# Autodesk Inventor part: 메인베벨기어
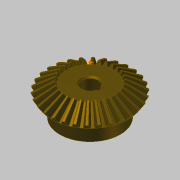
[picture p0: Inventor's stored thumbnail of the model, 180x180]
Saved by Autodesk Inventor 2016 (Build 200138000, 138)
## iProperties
Created: 2018-09
Part Number: 메인베벨기어
Material: 강철, 탄소
Document SubType Name: Modeling
Categories: <?xml version="1.0" encoding="UTF-16"?> <MemberInstance><Categories><FamilyTemplate><FamilyTemplateParameter ValueType="xs:double" Id="1" ObjectReferenceKey="da
Mass: 290.333 g
Surface Area: 107.709 cm^2
Volume: 36.8911 cm^3
Density: 7.87 g/cm^3
Appearance: 얼룩무늬
CustomPartVersion: 1
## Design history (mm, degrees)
node "맨 위 점"
node "메쉬 평면2"
sketch "톱니 본체 스케치"
  geometry: L1 (0, 0)-(28.669, -21.997); L2 (28.669, -21.997)-(31.109, -18.336); L3 (31.109, -18.336)-(0, 0); L4 (30, -20)-(0, 0); L5 (17.219, -13.212)-(18.685, -11.013); L6 (28.669, -21.997)-(17.219, -13.212); L7 (31.109, -18.336)-(18.685, -11.013); L8 (0, -39.387)-(0, 6.564) reference; L9 (0, -20)-(31.109, -20)
  constraints: 16 end point, 4 point on line, 3 perpendicular, 2 collinear, 1 horizontal alignment, 1 vertical alignment
  dimensions: "d0" = 60 diameter of L4.start L8 (= da_de); "d1" = 57.33744 diameter of L1.end L8 (= da_dfe); "d2" = 62.2188 diameter of L2.end L8 (= da_dae); "d3" = 14.4 distance between parallel lines of L2 L5 (= da_b); "d4" = 18.3359 vertical distance of L2.end L1.start (= da_ve)
revolve "톱니 본체" sketch "톱니 본체 스케치" stored, may be unused: angle "d5" = 90 deg
node "시작점"
node "톱니 평면"
sketch "시작 스케치"
  geometry: L1 (0, -23.505)-(0, 10.645) reference; L2 (-0.709, -2.928)-(0.709, -2.928); A1 r 19.188 centre (-19.457, -7.014) between (-0.709, -2.928) and (-3.232, 3.229); A2 r 19.188 centre (19.457, -7.014) between (3.232, 3.229) and (0.709, -2.928); A3 r 57.403 centre (0, -54.083) between (3.232, 3.229) and (-3.232, 3.229); 1 further point
  constraints: 6 point on circle, 3 centre point, 3 symmetric about line, 2 end point, 1 coincident, 1 perpendicular, 1 other
  dimensions: "d7" = 19.18795 radius of A1 (= fd_rr); "d8" = 19.45712 horizontal distance of point (0, -54.083) A1.centre (= fd_x); "d9" = 47.06905 vertical distance of point (0, -54.083) A1.centre (= fd_y); "d57" = 57.40327 radius of A3 (= 0.5 x fd_dva + 0.3 x da_he); "d58" = 51.15527 distance from line of A3.centre L2 (= 0.5 x fd_dva - 1.12 x da_he)
node "끝점"
  node "끝 평면"
sketch "3D 스케치 오른쪽"
  node "Helical Curve Right" dims "d65" = 229.90621 (computed from da_dm, da_delta, da_beta), "d66" = 31.5, "d67" = 60 (= da_de), "d68" = -9.82794 (= -da_delta), "d69" = 8.10972 (computed from fd_loft, da_delta)
node "끝 평면 오른쪽"
sketch "끝 스케치 오른쪽"
  geometry: L1 (0, -41.54)-(0, 13.178) reference; L2 (-0.422, -1.69)-(0.422, -1.69); A1 r 11.427 centre (-11.587, -4.123) between (-0.422, -1.69) and (-1.925, 1.977); A2 r 11.427 centre (11.587, -4.123) between (1.925, 1.977) and (0.422, -1.69); A3 r 34.184 centre (0, -32.153) between (1.925, 1.977) and (-1.925, 1.977); 1 further point
  constraints: 6 point on circle, 3 centre point, 3 symmetric about line, 2 end point, 1 coincident, 1 perpendicular, 1 other
  dimensions: "d70" = 11.58699 horizontal distance of A3.centre A1.centre (computed from fd_x, fd_ratio); "d71" = 28.03028 vertical distance of point (0, -32.153) A1.centre (computed from fd_y, fd_ratio); "d72" = 11.4267 radius of A1 (computed from fd_rr, fd_ratio); "d73" = 30.46369 distance from line of point (0, -32.153) L2 (computed from d58, fd_ratio); "d74" = 34.18446 radius of A3 (computed from d57, fd_ratio)
feature "로프트 오른쪽" sketch "끝 스케치 오른쪽" dims "d75" = 0, "d77" = 0, "d79" = 0, "d80" = 90 deg, "d85" = 20, "d92" = 90 deg, "d93" = 90 deg, "da_teethtype" = 0 [user parameter]
sketch "3D 스케치 왼쪽"
  node "Helical Curve Left" dims "d26" = 229.90621 (computed from da_dm, da_delta, da_beta), "d27" = 8.10972 (computed from fd_loft, da_delta), "d28" = 60 (= da_de), "d29" = -9.82794 (= -da_delta)
node "끝 평면 왼쪽"
sketch "끝 스케치 왼쪽" dims "d56" = 10.3728 (derived)
  geometry: L1 (0, -43.753)-(0, 15.405) reference; L2 (-0.422, -1.678)-(0.422, -1.678); A1 r 11.427 centre (-11.587, -4.111) between (-0.422, -1.678) and (-1.925, 1.988); A2 r 11.427 centre (11.587, -4.111) between (1.925, 1.988) and (0.422, -1.678); A3 r 34.184 centre (0, -32.142) between (1.925, 1.988) and (-1.925, 1.988); 2 further points; 1 other entity
  constraints: 6 point on circle, 3 centre point, 3 symmetric about line, 2 end point, 1 coincident, 2 other
  dimensions: "d30" = 11.4267 radius of A1 (computed from fd_rr, fd_ratio); "d31" = 11.58699 horizontal distance of point (0, -32.142) A1.centre (computed from fd_x, fd_ratio); "d32" = 28.03028 vertical distance of A1.centre point (0, -32.142) (computed from fd_y, fd_ratio); "d61" = 34.18446 radius of A3 (computed from d57, fd_ratio); "d62" = 30.46369 distance from line of point (0, -32.142) L2 (computed from d58, fd_ratio)
feature "로프트 왼쪽" sketch "끝 스케치 왼쪽" dims "d35" = 0, "d37" = 0, "d39" = 0, "d40" = 90 deg, "d84" = 10, "d90" = 90 deg, "d91" = 90 deg, "da_teethtype" = 0 [user parameter]
sketch "본체 스케치"
  geometry: L1 (0, -35.038)-(0, -19.531) reference; L2 (28.669, -21.997)-(17.219, -13.212) reference; L3 (17.219, -13.212)-(0, -13.212); L4 (28.669, -21.997)-(0, -21.997)
  constraints: 4 end point, 2 perpendicular, 2 point on line
revolve "본체 고정" sketch "본체 스케치" stored, may be unused: angle "d46" = 90 deg
feature "피치 지름" dims angle "d47" = 90 deg
sketch "스케치8"
  geometry: C1 r 22.5 at (0, 0); 1 further point
  constraints: 1 centre point, 1 coincident
  dimensions: "d94" = 45 diameter of C1
extrude "돌출1" join sketch "스케치8" distance "d95" = 13; taper "d96" = 0 deg
sketch "스케치9"
  geometry: 1 further point
hole "구멍1" sketch "스케치9" at (0, 0) diameter "d97" = 12; stored, may be unused: countersink angle "d101" = 90 deg, drill point angle "d103" = 118 deg; dims "d98" = 6, "d99" = 4, "d100" = 2, "d102" = 8
sketch "스케치10"
  geometry: L1 (5.657, 2)-(7.8, 2); L2 (7.8, 2)-(7.8, -2); L3 (7.8, -2)-(5.657, -2); A1 r 6 centre (0, 0) between (5.657, 2) and (5.657, -2) reference; 1 further point
  constraints: 6 end point, 2 parallel, 2 point on circle, 1 horizontal, 1 perpendicular
  dimensions: "d104" = 4 distance of L1.end L2.end; "d112" = 13.8 dimension on A1 L2
extrude "돌출2" cut sketch "스케치10" stored distance "d106" = 10; taper "d107" = 0 deg
chamfer "모따기1" distance "d108" = 1; stored, may be unused: second distance "d109" = 2, angle "d110" = 45 deg
fillet "모깎기1" dims "d111" = 2
body "Solid1"
feature "로프트" dims "d17" = 0, "d18" = 90 deg, "d19" = 0, "d20" = 90 deg, "d89" = 0, "da_teethtype" = 0 [user parameter]
pattern_circular "원형 패턴" dims angle "d22" = 360 deg, "d88" = 0, "da_teethtype" = 0 [user parameter]
pattern_circular "원형 패턴 오른쪽" dims angle "d82" = 360 deg, "da_teethtype" = 0 [user parameter]
pattern_circular "원형 패턴 왼쪽" dims angle "d42" = 360 deg, "da_teethtype" = 0 [user parameter]
sketch "끝 스케치"
  geometry: L1 (0, -15.359)-(0, 6.983) reference; L2 (-0.422, -1.69)-(0.422, -1.69); A1 r 11.427 centre (-11.587, -4.123) between (-0.422, -1.69) and (-1.925, 1.977); A2 r 11.427 centre (11.587, -4.123) between (1.925, 1.977) and (0.422, -1.69); A3 r 34.184 centre (0, -32.153) between (1.925, 1.977) and (-1.925, 1.977); 1 further point
  constraints: 6 point on circle, 3 centre point, 3 symmetric about line, 2 end point, 1 coincident, 1 other
  dimensions: "d12" = 11.4267 radius of A1 (computed from fd_rr, fd_ratio); "d15" = 11.58699 horizontal distance of A1.centre point (0, -32.153) (computed from fd_x, fd_ratio); "d16" = 28.03028 vertical distance of A1.centre point (0, -32.153) (computed from fd_y, fd_ratio); "d59" = 34.18446 radius of A3 (computed from d57, fd_ratio); "d60" = 30.46369 distance from line of A3.centre L2 (computed from d58, fd_ratio)
sketch "Sketch6"
  geometry: L1 (30, -20)-(0, 0) reference; L2 (0, -37.8)-(0, 6.3) reference
body "Srf1"
other parameters: "da_b" = 14.4 [user parameter; used in 2 equation terms], "da_de" = 60 [user parameter; used in 4 equation terms], "da_dae" = 62.2188 [user parameter; used in 2 equation terms], "da_dfe" = 57.33744 [user parameter; used in 1 equation term], "da_le" = 36.05551 [user parameter; used in 1 equation term], "da_omega" = 90 deg [user parameter; used in 1 equation term], "da_beta" = 0 [user parameter; used in 2 equation terms], "da_delta" = 9.82794 [user parameter; used in 8 equation terms], "da_alpha" = 20 deg [user parameter; used in 2 equation terms], "da_he" = 4.4 [user parameter; used in 4 equation terms], "da_ve" = 18.3359 [user parameter; used in 1 equation term], "fd_dv" = 108.16654 (computed from da_de, da_delta) [user parameter; used in 1 equation term], "fd_dva" = 112.16654 (computed from da_dae, da_delta) [user parameter; used in 3 equation terms], "fd_dvb" = 101.6433 (computed from fd_dv, da_alpha) [user parameter; used in 2 equation terms], "da_zv" = 540.83269 [user parameter; used in 1 equation term], "fd_loft" = 14.62 (= da_b + 0.05 x da_he) [user parameter; used in 4 equation terms], "fd_ratio" = 5.95514 (computed from da_le, fd_loft) [user parameter; used in 15 equation terms], "fd_rr" = 19.18795 (computed from fd_dd, fd_dvb) [user parameter; used in 6 equation terms], "fd_angle" = 0.29367 (computed from da_zv) [user parameter; used in 4 equation terms], "fd_x1" = 1.58802 (computed from da_dvw, fd_angle) [user parameter; used in 1 equation term], "fd_y1" = 54.05995 (computed from da_dvw, fd_angle) [user parameter; used in 1 equation term], "fd_x2" = 17.8691 (computed from fd_rr, fd_angle2, fd_angle) [user parameter; used in 1 equation term], "fd_y2" = 6.9909 (computed from fd_rr, fd_angle2, fd_angle) [user parameter; used in 1 equation term], "fd_x" = 19.45712 (= fd_x1 + fd_x2) [user parameter; used in 4 equation terms], "fd_y" = 47.06905 (= fd_y1 - fd_y2) [user parameter; used in 4 equation terms], "fd_angle2" = 3.43555 (computed from fd_dvb, fd_dd, da_alpha) [user parameter; used in 2 equation terms], "fd_dd" = 108.64654 (= fd_dva - 0.8 x da_he) [user parameter; used in 2 equation terms], "da_dvw" = 108.16654 [user parameter; used in 2 equation terms], "d11" = 14.62 (= fd_loft), "da_dm" = 48.01848 [user parameter; used in 2 equation terms], "da_x" = 0 [user parameter], "da_m" = 2 [user parameter], "d48" = 0, "d49" = 0, "d50" = 90 deg (= da_omega), "d51" = 6 deg (computed from da_z), "d52" = 0, "d53" = 0, "d54" = 0
